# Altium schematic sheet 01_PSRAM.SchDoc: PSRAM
size A4; Date: 17-03-2016; Author: A.B; CompanyName: STMicroelectronics; Organization: Microcontrollers Division; Address1: 12, Rue Jules HOROWITZ; Address2: 38019 Grenoble; Address3: FRANCE; DocumentNumber: 4; Revision: D-01; SheetNumber: 4; SheetTotal: 12; Project: STM32F413H-DISCO
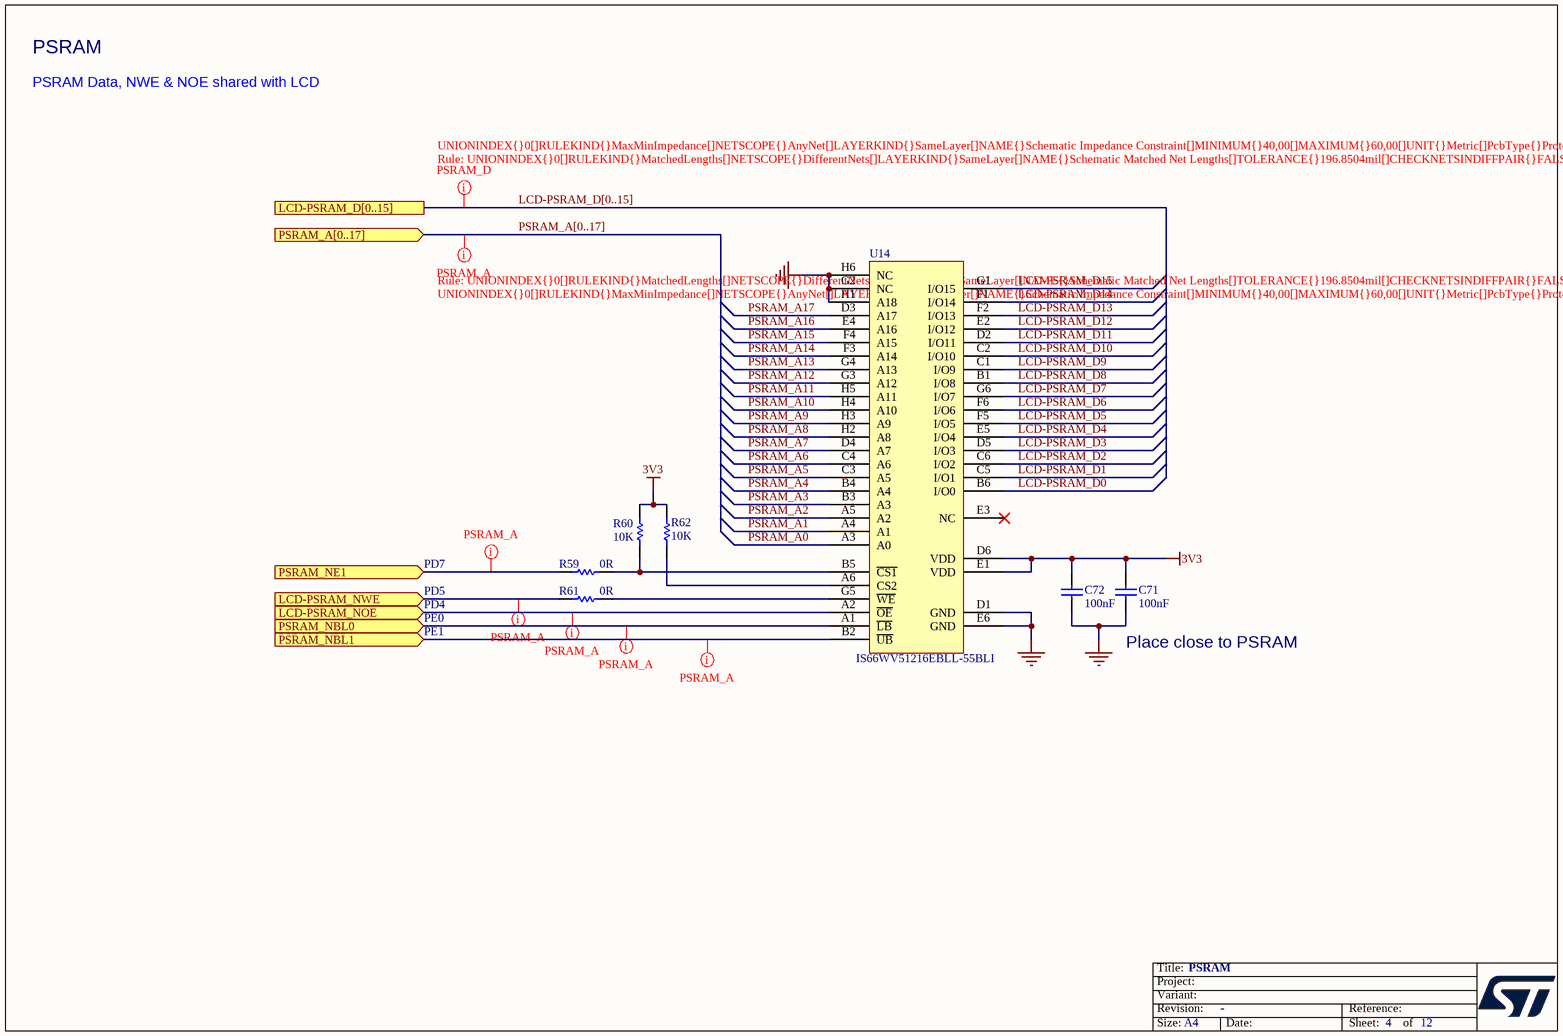
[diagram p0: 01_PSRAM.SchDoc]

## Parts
C71  100nF  [C0402]
C72  100nF  [C0402]
R59  0R  [R0402]
R60  10K  [R0402]
R61  0R  [R0402]
R62  10K  [R0402]
U14  IS66WV51216EBLL-55BLI  [ICC_MINI-BGA48_6X8_P075]

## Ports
LCD-PSRAM_D[0..15], LCD-PSRAM_NOE (in), LCD-PSRAM_NWE (in), PSRAM_A[0..17] (in), PSRAM_NBL0 (in), PSRAM_NBL1 (in), PSRAM_NE1 (in)

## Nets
3V3: C71.2 C72.2 R60.2 R62.2 U14.D6(VDD) U14.E1(VDD)
GND: C71.1 C72.1 U14.D1(GND) U14.E6(GND) U14.G2(NC) U14.H1(A18) U14.H6(NC)
LCD-PSRAM_D0: U14.B6(I/O0)
LCD-PSRAM_D1: U14.C5(I/O1)
LCD-PSRAM_D2: U14.C6(I/O2)
LCD-PSRAM_D3: U14.D5(I/O3)
LCD-PSRAM_D4: U14.E5(I/O4)
LCD-PSRAM_D5: U14.F5(I/O5)
LCD-PSRAM_D6: U14.F6(I/O6)
LCD-PSRAM_D7: U14.G6(I/O7)
LCD-PSRAM_D8: U14.B1(I/O8)
LCD-PSRAM_D9: U14.C1(I/O9)
LCD-PSRAM_D10: U14.C2(I/O10)
LCD-PSRAM_D11: U14.D2(I/O11)
LCD-PSRAM_D12: U14.E2(I/O12)
LCD-PSRAM_D13: U14.F2(I/O13)
LCD-PSRAM_D14: U14.F1(I/O14)
LCD-PSRAM_D15: U14.G1(I/O15)
LCD-PSRAM_NOE: U14.A2(~{OE}) ; port LCD-PSRAM_NOE
LCD-PSRAM_NWE: R61.1 ; port LCD-PSRAM_NWE
PSRAM_A0: U14.A3(A0)
PSRAM_A1: U14.A4(A1)
PSRAM_A2: U14.A5(A2)
PSRAM_A3: U14.B3(A3)
PSRAM_A4: U14.B4(A4)
PSRAM_A5: U14.C3(A5)
PSRAM_A6: U14.C4(A6)
PSRAM_A7: U14.D4(A7)
PSRAM_A8: U14.H2(A8)
PSRAM_A9: U14.H3(A9)
PSRAM_A10: U14.H4(A10)
PSRAM_A11: U14.H5(A11)
PSRAM_A12: U14.G3(A12)
PSRAM_A13: U14.G4(A13)
PSRAM_A14: U14.F3(A14)
PSRAM_A15: U14.F4(A15)
PSRAM_A16: U14.E4(A16)
PSRAM_A17: U14.D3(A17)
PSRAM_NBL0: U14.A1(~{LB}) ; port PSRAM_NBL0
PSRAM_NBL1: U14.B2(~{UB}) ; port PSRAM_NBL1
PSRAM_NE1: R59.1 ; port PSRAM_NE1
NetR59_2: R59.2 R60.1 U14.B5(~{CS1})
NetR61_2: R61.2 U14.G5(~{WE})
NetR62_1: R62.1 U14.A6(CS2)

Not connected (* = marked no-connect by the designer): U14 E3(NC)*

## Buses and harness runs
bus LCD-PSRAM_D[0..15] = port LCD-PSRAM_D[0..15]
bus PSRAM_A[0..17] = port PSRAM_A[0..17]

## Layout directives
rule Matched Net Lengths [Tolerance = 5mm]; rule Impedance Constraint [Min = 40.00    Max = 60.00    ]: (no net found under the mark), LCD-PSRAM_NOE, LCD-PSRAM_NWE, PSRAM_NBL0, PSRAM_NBL1, PSRAM_NE1

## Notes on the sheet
- PSRAM
- PSRAM Data, NWE & NOE shared with LCD
- PD7
- PD5
- PD4
- PE0
- PE1
- (near C71) Place close to PSRAM

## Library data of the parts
C71 C72 = Cap_100nF_X7R_10%_0402: Capacitor,100nF,16V,X7R,10%,0402,YAGEO; Manuf_Part_1: CC0402KRX7R7BB104; Fitted: YES; Ordered_By: Subcon
R59 R61 = Res_0_5%_0402: Resistor,0R,0402,5%,YAGEO; Manuf_Part_1: RC0402JR-070RL; Fitted: YES; Order_Code: 2363467; Ordered_By: Subcon
R60 R62 = Res_10K_1%_0402: Resistor,10K,0402,1%,YAGEO; Manuf_Part_1: RC0402FR-0710KL; Fitted: YES; Ordered_By: subcon
U14 = IS66WV51216EBLL-55BLI: IC SRAM 8MBIT 55NS 48MINIBGA 6mm x 8mm; Manuf_1: ISSI, Integrated Silicon Solution Inc; Fitted: YES; ECCN_US/EU: EAR99/NEC; Ordered_By: Subcon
